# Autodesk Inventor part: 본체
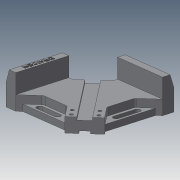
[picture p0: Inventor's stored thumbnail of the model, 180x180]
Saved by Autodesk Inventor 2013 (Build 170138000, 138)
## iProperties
Created: 2020-05
Part Number: 본체
Material: Generic
Document SubType Name: Modeling
Designer: user
Density: 1 g/cm^3
Author: user
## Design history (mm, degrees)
sketch "스케치1"
  geometry: L1 (60, -60)-(-60, -60); L2 (-60, -60)-(-60, 60); L3 (-60, 60)-(60, 60); L4 (60, 60)-(60, -60); L5 (60, -60)-(-60, 60); L6 (-60, -60)-(60, 60); 1 further point
  constraints: 12 end point, 2 midpoint, 2 parallel, 1 horizontal, 1 perpendicular
  dimensions: "d0" = 120 distance of L2.end L3.end; "d1" = 120 distance of L1.end L2.end
extrude "돌출1" new body sketch "스케치1" distance "d2" = 18; taper "d3" = 0 deg
sketch "스케치2"
  geometry: L1 (-60, -60)-(60, -60) reference; L2 (60, -60)-(60, 60) reference; L3 (60, -60)-(80, -60); L4 (31.716, -60)-(60, -60); L5 (60, -31.716)-(60, -60); L6 (31.716, -60)-(60, -31.716); 1 further point
  constraints: 8 end point, 2 point on line, 1 collinear, 1 horizontal, 1 perpendicular
extrude "돌출2" cut sketch "스케치2" stored distance "d6" = 0; taper "d7" = 0 deg
sketch "스케치4"
  geometry: L1 (-60, 60)-(-10, 60); L2 (-10, 60)-(-10, 38.284); L3 (-38.284, 10)-(-60, 10); L4 (-60, 10)-(-60, 60); L5 (-38.284, 10)-(-10, 38.284); 1 further point
  constraints: 10 end point, 2 parallel, 1 horizontal, 1 perpendicular
extrude "돌출4" cut sketch "스케치4" distance "d16" = 18; taper "d17" = 0 deg
sketch "스케치3"
  geometry: L1 (0, 0)-(-40, 0) reference; L2 (-40, 18)-(0, 18) reference; L3 (-28, 18)-(-12, 18); L4 (-12, 18)-(-12, 14.5); L5 (-12, 14.5)-(-28, 14.5); L6 (-28, 14.5)-(-28, 18); L7 (-26, 3)-(-14, 3); L8 (-14, 3)-(-14, 0); L9 (-14, 0)-(-26, 0); L10 (-26, 0)-(-26, 3); 3 further points
  constraints: 16 end point, 4 midpoint, 4 parallel, 2 horizontal, 2 perpendicular
  dimensions: "d8" = 16 distance of L4.end L5.end; "d9" = 3.5 distance of L3.end L4.end; "d10" = 12 distance of L8.end L9.end; "d11" = 3 distance of L7.end L8.end
extrude "돌출3" cut sketch "스케치3" stored distance "d12" = 18; taper "d13" = 0 deg
sketch "스케치5"
  geometry: L1 (-60, -60)-(31.716, -60) reference; L2 (-60, 10)-(-45, 10); L3 (-45, 10)-(-45, -60); L4 (-45, -60)-(-60, -60); L5 (-60, -60)-(-60, 10); L6 (60, 60)-(-10, 60) reference; L7 (-10, 60)-(60, 60); L8 (60, 60)-(60, 45); L9 (60, 45)-(-10, 45); L10 (-10, 45)-(-10, 60); 1 further point
  constraints: 16 end point, 4 parallel, 2 horizontal, 2 perpendicular, 1 point on line
  dimensions: "d18" = 15 distance of L3.end L4.end; "d19" = 15 distance of L7.end L8.end
extrude "돌출5" join sketch "스케치5" distance "d20" = 24; taper "d21" = 0 deg
sketch "스케치7"
  geometry: L1 (-45, -60)-(31.716, -60) reference; L2 (31.716, -60)-(40.201, -51.515) reference; L3 (-38.284, 10)-(-45, 10) reference; L4 (-45, -60)-(-25, -40); L5 (-25, -40)-(11.716, -40); L6 (11.716, -40)-(31.716, -60); L7 (-60, 10)-(-60, -60) reference; 1 further point
  constraints: 6 end point, 4 point on line, 1 parallel, 1 perpendicular
  dimensions: "d37" = 20 distance between parallel lines of L1 L5; "d40" = 90 deg angle of L2 L6
extrude "돌출7" cut sketch "스케치7" stored distance "d41" = 24; taper "d42" = 0 deg
sketch "스케치8"
  geometry: L1 (45, 60)-(25, 40) reference; L2 (25, 40)-(-11.716, 40) reference; L3 (-11.716, 40)-(-31.716, 60) reference; L4 (40, 55)-(-26.716, 55); 1 further point
  constraints: 2 end point, 2 point on line
extrude "돌출8" join sketch "스케치8" distance "d44" = 8; taper "d45" = 0 deg
sketch "스케치9"
  geometry: L1 (-22, -44)-(6, -44); L2 (6, -44)-(6, -52); L3 (6, -52)-(-22, -52); L4 (-22, -52)-(-22, -44); L5 (-60, -60)-(-45, -60) reference; L6 (-60, 10)-(-60, -60) reference; C1 r 4 at (-22, -48); C2 r 4 at (6, -48); 1 further point
  constraints: 8 end point, 2 centre point, 2 midpoint, 2 parallel, 1 horizontal, 1 perpendicular
  dimensions: "d46" = 28 distance of L2.end L3.end; "d47" = 8 distance of L1.end L2.end; "d48" = 8 diameter of C1; "d49" = 8 diameter of C2; "d50" = 12 distance from line of L5 C1.centre; "d51" = 38 distance from line of L6 C1.centre
extrude "돌출9" cut sketch "스케치9" stored distance "d52" = 0; taper "d53" = 0 deg
node "작업 평면1"
sketch "스케치10"
  geometry: L1 (0, 0)-(15, 0) reference; L2 (0, -42)-(0, 0) reference; L3 (5, 0)-(0, -15); 1 further point
  constraints: 2 end point, 2 point on line
  dimensions: "d54" = 5 distance of L1.start L3.start; "d55" = 15 distance of L1.start L3.end
extrude "돌출10" cut sketch "스케치10" stored distance "d56" = 8; taper "d57" = 0 deg
sketch "스케치12"
  geometry: L1 (31.716, 60)-(26.716, 55) reference; L2 (41.615, 50.101)-(31.716, 60) reference; 3 further points
  dimensions: "d60" = 6 distance from line of L2 point (31.716, 51.515); "d61" = 18 distance from line of L2 point (23.23, 43.029); "d62" = 6 distance from line of L1 point (31.716, 51.515); "d63" = 6 distance from line of L1 point (23.23, 43.029)
hole "구멍1" sketch "스케치12" at (31.716, 51.515), (23.23, 43.029) diameter "d64" = 4.5; stored, may be unused: countersink angle "d68" = 90 deg, drill point angle "d70" = 118 deg; dims "d65" = 6, "d66" = 8, "d67" = 10, "d69" = 8
fillet "모깎기1" dims "d71" = 5
sketch "스케치14"
  geometry: L1 (-45, -60)-(-45, 10) reference; L2 (-45, 10)-(-55, 10) reference; L3 (-46.996, -5)-(-46.996, -46.479); L4 (-46.996, -46.479)-(-53, -46.479); L5 (-53, -46.479)-(-53, -5); L6 (-53, -5)-(-46.996, -5); 1 further point
  constraints: 2 other
  dimensions: "d74" = 15 distance between parallel lines of L2 L6; "d75" = 8 distance between parallel lines of L5 L1
feature "엠보싱1" sketch "스케치14" dims "d76" = 0.5, "d77" = 0
node "솔리드1"
mirror "대칭1"
mirror "대칭2"
mirror "대칭3"
